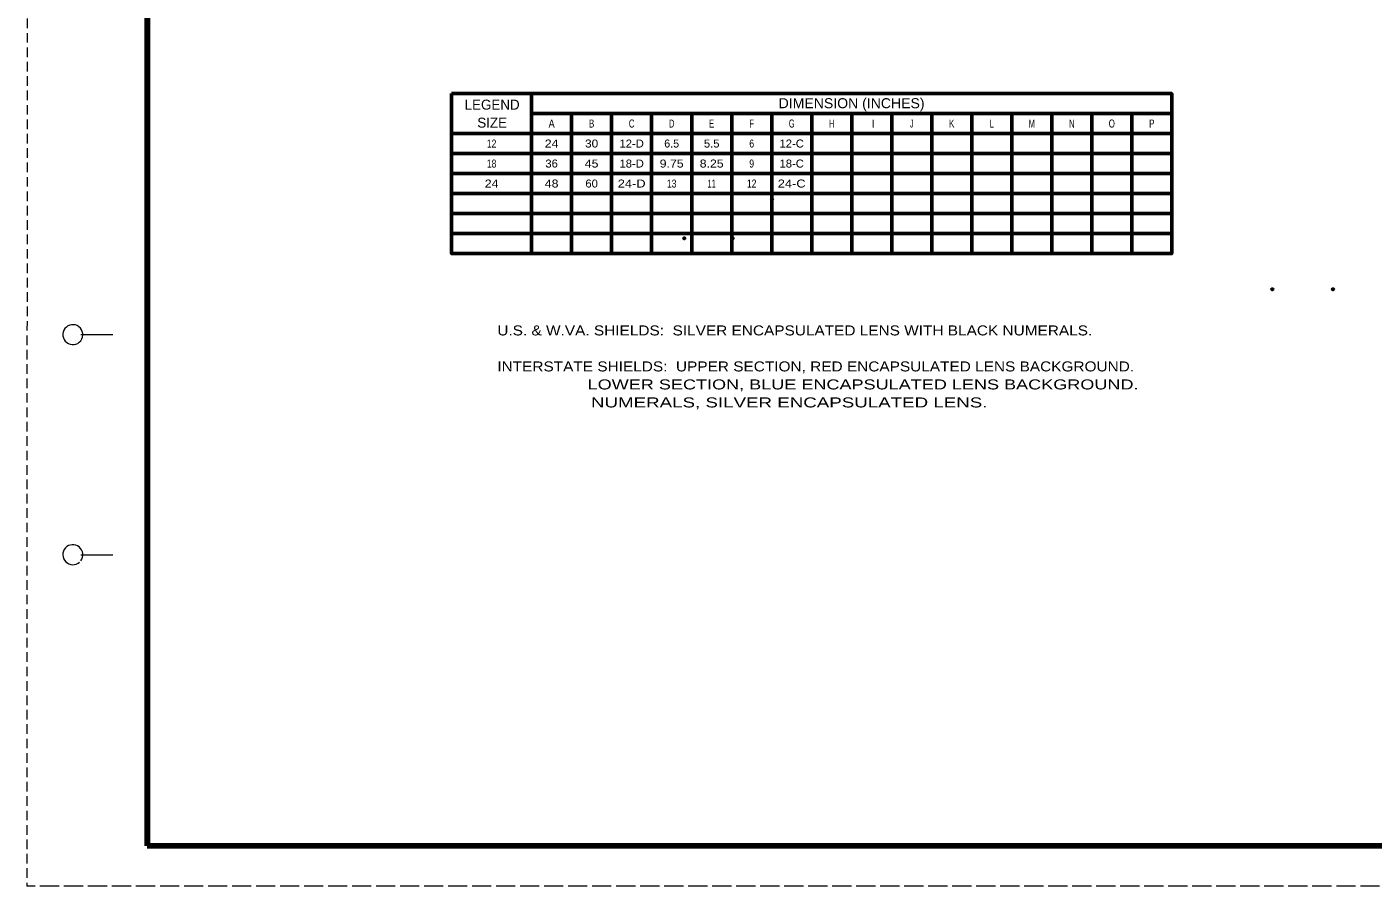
# Model space of a CAD drawing. Extents: x -55 to 625, y -354 to 86.
# Drawn here: x -54.9 to 281.5, y -353.6 to -138.9 of the extents above; entities that cross this region are included whole.
import ezdxf
from ezdxf.enums import TextEntityAlignment as Align

# ---------------------------------------------------------------- set-up
doc = ezdxf.new("R2010")
doc.units = 0
doc.header["$LTSCALE"] = 0.8
doc.header["$PDMODE"] = 32
doc.header["$PDSIZE"] = 0.4
doc.linetypes.add('LONG_DASHED', pattern=[7.5, 6, -1.5])
doc.linetypes.add('MEDIUM_DASHED', pattern=[4.5, 3, -1.5])
doc.layers.add('1', color=7, linetype='Continuous', lineweight=40)
doc.layers.add('61', color=7, linetype='Continuous', lineweight=35)

msp = doc.modelspace()

# ---------------------------------------------------------------- linework, layer by layer
at = {"layer": '1', "linetype": 'MEDIUM_DASHED', "lineweight": 13}
msp.add_line((-54.8373, 86.3965), (-54.8973, -353.6435), dxfattribs=at)
at = {"layer": '1', "lineweight": 53}
for p, q in [((71.2423, -195.529), (71.2423, -155.529)), ((71.2423, -160.529), (231.2423, -160.529)), ((81.2423, -195.529), (81.2423, -160.529)), ((91.2423, -195.529), (91.2423, -160.529)), ((101.2423, -195.529), (101.2423, -160.529)), ((111.2423, -195.529), (111.2423, -160.529)), ((121.2423, -195.529), (121.2423, -160.529)), ((131.2423, -195.529), (131.2423, -160.529)), ((141.2423, -195.529), (141.2423, -160.529)), ((151.2423, -195.529), (151.2423, -160.529)), ((161.2423, -195.529), (161.2423, -160.529)), ((171.2423, -195.529), (171.2423, -160.529)), ((181.2423, -195.529), (181.2423, -160.529)), ((191.2423, -195.529), (191.2423, -160.529)), ((201.2423, -195.529), (201.2423, -160.529)), ((211.2423, -195.529), (211.2423, -160.529)), ((221.2423, -195.529), (221.2423, -160.529)), ((151.2423, -165.529), (161.2423, -165.529)), ((158.7423, -165.529), (173.7423, -165.529)), ((51.2423, -170.529), (231.2423, -170.529)), ((51.2423, -175.529), (231.2423, -175.529)), ((51.2423, -180.529), (231.2423, -180.529)), ((51.2423, -185.529), (231.2423, -185.529)), ((51.2423, -190.529), (231.2423, -190.529))]:
    msp.add_line(p, q, dxfattribs=at)
msp.add_lwpolyline([(51.2423, -155.529), (231.2423, -155.529), (231.2423, -195.529), (51.2423, -195.529)], close=True, dxfattribs=at)
for points in [[(51.2423, -165.529), (71.2423, -165.529), (81.2423, -165.529), (91.2423, -165.529), (101.2423, -165.529), (111.2423, -165.529), (121.2423, -165.529), (131.2423, -165.529), (141.2423, -165.529), (153.7423, -165.529)], [(171.2423, -165.529), (181.2423, -165.529), (191.2423, -165.529), (201.2423, -165.529), (211.2423, -165.529), (221.2423, -165.529), (231.2423, -165.529)]]:
    msp.add_lwpolyline(points, dxfattribs=at)
at = {"layer": '1'}
for p in [(131.3208, -181.8756), (109.3899, -191.7061), (121.4903, -191.7061), (256.3804, -204.4469), (271.5057, -204.4469)]:
    msp.add_point(p, dxfattribs=at)
at = {"layer": '61', "lineweight": 13}
for p, q in [((-41.4173, -215.7835), (-33.4173, -215.7835)), ((-41.3973, -270.8035), (-33.4173, -270.8035))]:
    msp.add_line(p, q, dxfattribs=at)
at = {"layer": '61', "lineweight": 158}
msp.add_line((614.2227, -343.6435), (-24.8373, -343.6235), dxfattribs=at)
at = {"layer": '61', "linetype": 'LONG_DASHED', "lineweight": 13}
msp.add_line((625.1627, -353.6235), (-54.8973, -353.6435), dxfattribs=at)
at = {"layer": '61', "lineweight": 158}
msp.add_lwpolyline([(614.2027, 76.3965), (-24.8373, 76.3965), (-24.8373, -343.6235)], dxfattribs=at)
at = {"layer": '61', "lineweight": 13}
for centre, start, end in [((-43.4196, -215.8022), 322.67175, 321.71615), ((-43.4196, -270.8022), 323.13009, 312.31439)]:
    msp.add_arc(centre, 2.5, start, end, dxfattribs=at)

# ---------------------------------------------------------------- texts
at = {"layer": '1'}
for s, height, p in [('LEGEND', 2.5, (61.3756, -159.5565)), ('SIZE', 2.5, (61.3757, -164.0565)), ('I', 2, (156.6106, -164.029)), ('6.5', 2, (106.2423, -169.029))]:
    msp.add_text(s, height=height, dxfattribs=at).set_placement(p, align=Align.CENTER)
for s, height, width, p in [('DIMENSION (INCHES)', 2.5, 1.05, (151.2125, -159.197)), ('A', 2, 0.85, (76.2424, -164.029)), ('B', 2, 0.75, (86.2424, -164.029)), ('C', 2, 0.75, (96.2423, -164.029)), ('D', 2, 0.7, (106.2424, -164.029)), ('E', 2, 0.7, (116.2424, -164.029)), ('F', 2, 0.75, (126.2424, -164.029)), ('G', 2, 0.7, (136.2423, -164.029)), ('H', 2, 0.7, (146.2424, -164.029)), ('J', 2, 0.7, (166.2424, -164.029)), ('K', 2, 0.75, (176.2424, -164.029)), ('L', 2, 0.75, (186.2424, -164.029)), ('M', 2, 0.7, (196.2423, -164.029)), ('N', 2, 0.7, (206.2424, -164.029)), ('O', 2, 0.75, (216.2423, -164.029)), ('P', 2, 0.75, (226.2424, -164.029)), ('12', 2, 0.8, (61.2424, -169.029)), ('24', 2, 1.15, (76.2424, -169.029)), ('30', 2, 1.1, (86.2423, -169.029)), ('12-D', 2, 1.05, (96.2424, -169.029)), ('5.5', 2, 1.05, (116.2423, -169.029)), ('6', 2, 0.8, (126.2424, -169.029)), ('12-C', 2, 1.05, (136.2424, -169.029)), ('18', 2, 0.8, (61.2424, -174.029)), ('36', 2, 1.05, (76.2423, -174.029)), ('45', 2, 1.15, (86.2424, -174.029)), ('18-D', 2, 1.05, (96.2424, -174.029)), ('9.75', 2, 1.15, (106.2424, -174.029)), ('8.25', 2, 1.15, (116.2424, -174.029)), ('9', 2, 0.8, (126.2424, -174.029)), ('18-C', 2, 1.05, (136.2424, -174.029)), ('24', 2, 1.15, (61.2424, -179.029)), ('48', 2, 1.15, (76.2424, -179.029)), ('60', 2, 1.05, (86.2423, -179.029)), ('24-D', 2, 1.2, (96.2423, -179.029)), ('13', 2, 0.8, (106.2424, -179.029)), ('11', 2, 0.55, (116.2423, -179.029)), ('12', 2, 0.8, (126.2424, -179.029)), ('24-C', 2, 1.2, (136.2423, -179.029))]:
    msp.add_text(s, height=height, dxfattribs=dict(at, width=width)).set_placement(p, align=Align.CENTER)
for s, width, p in [('U.S. & W.VA. SHIELDS:  SILVER ENCAPSULATED LENS WITH BLACK NUMERALS.', 1.15, (62.6697, -215.9968)), ('INTERSTATE SHIELDS:  UPPER SECTION, RED ENCAPSULATED LENS BACKGROUND.', 1.15, (62.6697, -224.9968)), ('                  LOWER SECTION, BLUE ENCAPSULATED LENS BACKGROUND.', 1.35, (62.6697, -229.4968)), ('                  NUMERALS, SILVER ENCAPSULATED LENS.', 1.4, (62.6697, -233.9968))]:
    msp.add_text(s, height=2.5, dxfattribs=dict(at, width=width)).set_placement(p)

doc.saveas('drawing.dxf')
